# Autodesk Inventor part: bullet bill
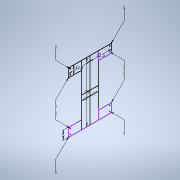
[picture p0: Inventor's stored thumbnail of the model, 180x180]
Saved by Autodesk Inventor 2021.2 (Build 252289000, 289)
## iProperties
Created: 2021-01
Part Number: bullet bill
Material: Generic
Document SubType Name: Modeling
Designer: josep
Density: 1 g/cm^3
Appearance: Default
Author: josep
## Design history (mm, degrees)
sketch "Sketch1"
  geometry: L1 (0, 0)-(35, 0); L2 (35, 0)-(35, -11.5); L3 (35, 0)-(35, 11.5); L4 (0, 11.5)-(0, -11.5); L5 (34, 12.5)-(31, 12.5); L6 (34, -12.5)-(31, -12.5); L7 (1, 12.5)-(4, 12.5); L8 (1, -12.5)-(4, -12.5); L9 (17.5, 0)-(17.5, 5); L10 (17.5, 0)-(17.5, -5); L11 (17.5, 5)-(29, 5); L12 (30, 6)-(30, 11.5); L13 (17.5, 5)-(6, 5); L14 (5, 6)-(5, 11.5); L15 (17.5, -5)-(29, -5); L16 (17.5, -5)-(6, -5); L17 (5, -6)-(5, -11.5); L18 (30, -6)-(30, -11.5); L19 (29, 5)-(30, 5); L20 (30, 5)-(30, 6); L21 (29, -5)-(30, -5); L22 (30, -5)-(30, -6); L23 (5, 6)-(5, 5); L24 (6, 5)-(5, 5); L25 (5, -6)-(5, -5); L26 (5, -5)-(6, -5); L27 (5, 5)-(0, 5); L28 (5, -5)-(0, -5); L29 (30, 5)-(35, 5); L30 (30, -5)-(35, -5); A1 r 1 centre (31, 11.5) between (31, 12.5) and (30, 11.5); A2 r 1 centre (4, 11.5) between (5, 11.5) and (4, 12.5); A3 r 1 centre (1, 11.5) between (1, 12.5) and (0, 11.5); A4 r 1 centre (1, -11.5) between (0, -11.5) and (1, -12.5); A5 r 1 centre (4, -11.5) between (4, -12.5) and (5, -11.5); A6 r 1 centre (31, -11.5) between (30, -11.5) and (31, -12.5); A7 r 1 centre (34, -11.5) between (34, -12.5) and (35, -11.5); A8 r 1 centre (34, 11.5) between (35, 11.5) and (34, 12.5); 5 further points
  constraints: 60 end point, 20 point on line, 16 point on circle, 16 tangent, 10 horizontal, 9 perpendicular, 8 centre point, 6 vertical, 1 midpoint, 1 parallel
  dimensions: "d0" = 35 distance of L1.start L1.end; "d1" = 12.5 distance of L1.end point (35, -12.5); "d2" = 12.5 distance of L1.end point (35, 12.5); "d3" = 5 distance of point (35, 12.5) point (30, 12.5); "d4" = 5 distance of point (0, 12.5) point (5, 12.5); "d5" = 5 distance of L9.start L9.end; "d6" = 5 distance of L9.start L10.end; "d7" = 1 radius of A1; "d10" = 1 radius of A2; "d11" = 1 radius of A3; "d12" = 1 radius of A4; "d13" = 1 radius of A5; "d16" = 1 radius of A6; "d17" = 1 radius of A7; "d18" = 1 radius of A8
